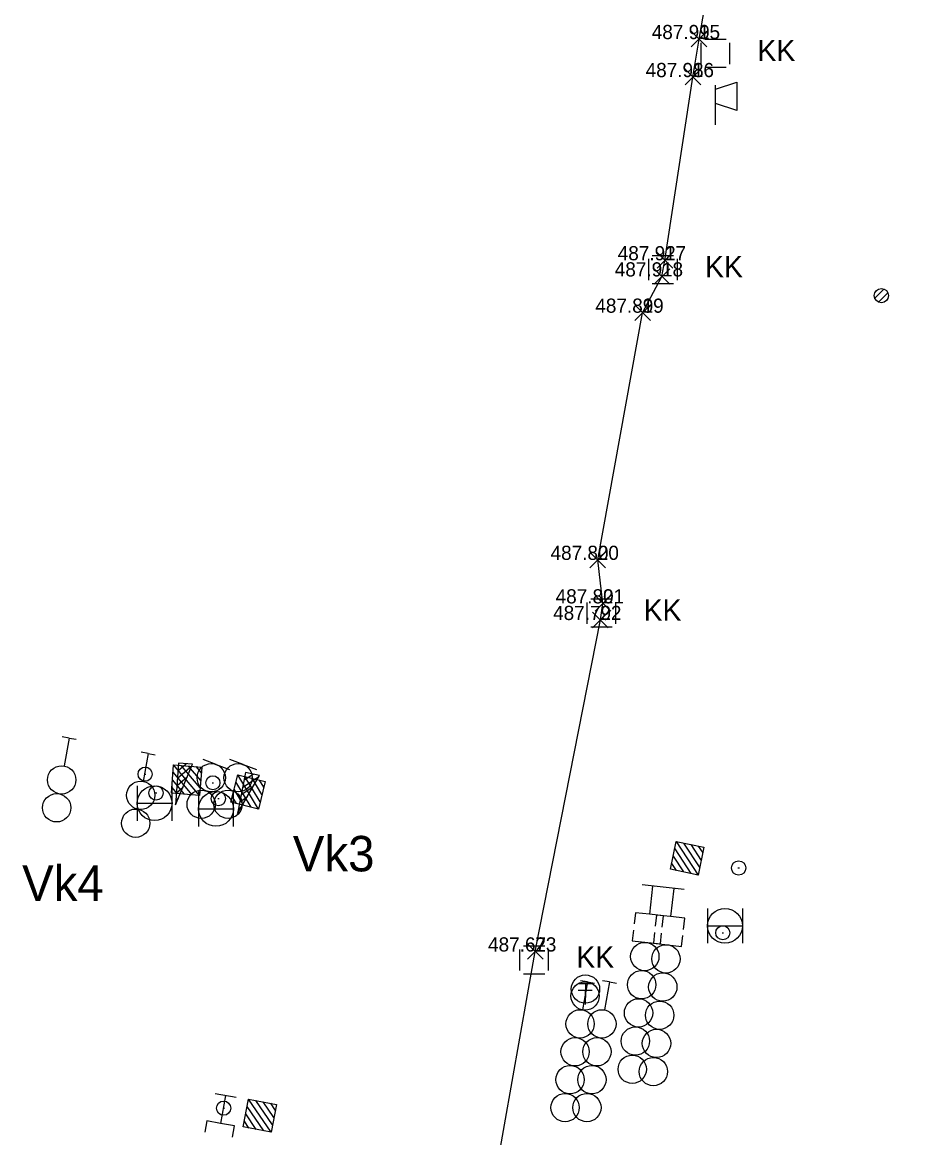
# Model space of a CAD drawing. Extents: x -874058 to -854960, y -10531873 to -1049126.
# Drawn here: x -866538.1 to -866474.7, y -1050102.6 to -1050024 of the extents above; entities that cross this region are included whole.
import ezdxf

# ---------------------------------------------------------------- set-up
doc = ezdxf.new("R2010")
doc.units = 0
for name, color, linetype in [('Vrstva 2', 7, 'Continuous'), ('Vrstva 3', 7, 'Continuous'), ('Vrstva 32', 7, 'Continuous'), ('Vrstva 33', 7, 'Continuous'), ('Vrstva 35', 7, 'Continuous'), ('Vrstva 36', 7, 'Continuous'), ('Vrstva 50', 7, 'Continuous'), ('Vrstva 6', 7, 'Continuous'), ('Vrstva 60', 7, 'Continuous'), ('Vrstva 61', 7, 'Continuous')]:
    doc.layers.add(name, color=color, linetype=linetype)

msp = doc.modelspace()

# ---------------------------------------------------------------- linework, layer by layer
at = {"layer": 'Vrstva 3'}
for p, q in [((-866526.085, -1050078.435), (-866527.432, -1050076.852)), ((-866525.557, -1050078.477), (-866527.39, -1050076.323)), ((-866527.112, -1050077.254), (-866526.091, -1050076.381)), ((-866527.073, -1050076.73), (-866526.494, -1050076.246)), ((-866527.036, -1050076.215), (-866527.018, -1050076.208)), ((-866525.514, -1050077.949), (-866526.862, -1050076.366)), ((-866525.472, -1050077.419), (-866526.332, -1050076.408)), ((-866525.429, -1050076.891), (-866525.804, -1050076.451)), ((-866522.308, -1050076.883), (-866522.29, -1050076.878)), ((-866526.614, -1050078.392), (-866527.475, -1050077.381)), ((-866527.15, -1050077.777), (-866526.41, -1050077.148)), ((-866521.924, -1050079.315), (-866522.997, -1050077.534)), ((-866521.41, -1050079.442), (-866522.869, -1050077.019)), ((-866522.511, -1050077.904), (-866521.391, -1050077.163)), ((-866522.409, -1050077.389), (-866521.775, -1050076.98)), ((-866521.282, -1050078.928), (-866522.355, -1050077.147)), ((-866521.154, -1050078.413), (-866521.839, -1050077.275)), ((-866521.027, -1050077.898), (-866521.325, -1050077.403)), ((-866529.972, -1050077.798), (-866529.972, -1050080.262)), ((-866527.142, -1050078.35), (-866527.517, -1050077.909)), ((-866527.508, -1050077.798), (-866527.508, -1050080.262)), ((-866527.189, -1050078.301), (-866526.721, -1050077.897)), ((-866525.642, -1050078.198), (-866525.642, -1050080.662)), ((-866523.178, -1050078.198), (-866523.178, -1050080.662)), ((-866522.44, -1050079.187), (-866523.125, -1050078.049)), ((-866522.613, -1050078.419), (-866521.801, -1050077.885)), ((-866529.972, -1050079.03), (-866527.508, -1050079.03)), ((-866527.228, -1050078.824), (-866527.048, -1050078.662)), ((-866522.954, -1050079.059), (-866523.252, -1050078.564)), ((-866522.817, -1050079.449), (-866522.619, -1050079.31)), ((-866522.715, -1050078.934), (-866522.201, -1050078.591)), ((-866525.642, -1050079.43), (-866523.178, -1050079.43)), ((-866492.032, -1050082.252), (-866490.893, -1050083.991)), ((-866491.924, -1050081.733), (-866490.374, -1050084.099)), ((-866491.405, -1050081.841), (-866490.266, -1050083.58)), ((-866490.885, -1050081.949), (-866490.158, -1050083.06)), ((-866490.366, -1050082.058), (-866490.049, -1050082.541)), ((-866492.14, -1050082.771), (-866491.413, -1050083.882)), ((-866492.249, -1050083.29), (-866491.932, -1050083.774)), ((-866489.722, -1050086.448), (-866489.722, -1050088.912)), ((-866487.258, -1050086.448), (-866487.258, -1050088.912)), ((-866489.722, -1050087.68), (-866487.258, -1050087.68)), ((-866498.83, -1050091.74), (-866497.83, -1050091.74)), ((-866498.33, -1050091.74), (-866498.33, -1050092.74)), ((-866498.856, -1050092.224), (-866497.856, -1050092.224)), ((-866498.356, -1050092.224), (-866498.356, -1050093.224)), ((-866521.032, -1050102.136), (-866522.203, -1050100.418)), ((-866520.511, -1050102.235), (-866522.104, -1050099.897)), ((-866520.412, -1050101.714), (-866521.583, -1050099.996)), ((-866520.314, -1050101.192), (-866521.061, -1050100.095)), ((-866520.215, -1050100.672), (-866520.541, -1050100.194)), ((-866521.554, -1050102.037), (-866522.301, -1050100.94)), ((-866522.074, -1050101.939), (-866522.4, -1050101.461))]:
    msp.add_line(p, q, dxfattribs=at)
for points in [[(-866527.55, -1050078.317), (-866527.39, -1050076.323), (-866525.396, -1050076.483), (-866525.557, -1050078.477)], [(-866527.55, -1050078.317), (-866527.39, -1050076.323), (-866525.396, -1050076.483), (-866525.557, -1050078.477)], [(-866523.351, -1050078.961), (-866522.869, -1050077.019), (-866520.928, -1050077.501), (-866521.41, -1050079.442)], [(-866523.351, -1050078.961), (-866522.869, -1050077.019), (-866520.928, -1050077.501), (-866521.41, -1050079.442)], [(-866489.966, -1050082.141), (-866490.374, -1050084.099), (-866492.332, -1050083.691), (-866491.924, -1050081.733)], [(-866489.966, -1050082.141), (-866490.374, -1050084.099), (-866492.332, -1050083.691), (-866491.924, -1050081.733)], [(-866522.476, -1050101.863), (-866522.104, -1050099.897), (-866520.139, -1050100.27), (-866520.511, -1050102.235)], [(-866522.476, -1050101.863), (-866522.104, -1050099.897), (-866520.139, -1050100.27), (-866520.511, -1050102.235)]]:
    msp.add_lwpolyline(points, close=True, dxfattribs=at)
for points in [[(-866527.55, -1050078.317), (-866527.39, -1050076.323), (-866525.396, -1050076.483), (-866525.557, -1050078.477), (-866527.55, -1050078.317)], [(-866527.55, -1050078.317), (-866527.39, -1050076.323), (-866525.396, -1050076.483), (-866525.557, -1050078.477), (-866527.55, -1050078.317)], [(-866527.251, -1050079.147), (-866526.049, -1050076.279), (-866527.035, -1050076.206), (-866527.251, -1050079.147)], [(-866527.251, -1050079.147), (-866526.049, -1050076.279), (-866527.035, -1050076.206), (-866527.251, -1050079.147)], [(-866522.88, -1050079.767), (-866521.337, -1050077.066), (-866522.307, -1050076.874), (-866522.88, -1050079.767)], [(-866522.88, -1050079.767), (-866521.337, -1050077.066), (-866522.307, -1050076.874), (-866522.88, -1050079.767)], [(-866523.351, -1050078.961), (-866522.869, -1050077.019), (-866520.928, -1050077.501), (-866521.41, -1050079.442), (-866523.351, -1050078.961)], [(-866523.351, -1050078.961), (-866522.869, -1050077.019), (-866520.928, -1050077.501), (-866521.41, -1050079.442), (-866523.351, -1050078.961)], [(-866489.966, -1050082.141), (-866490.374, -1050084.099), (-866492.332, -1050083.691), (-866491.924, -1050081.733), (-866489.966, -1050082.141)], [(-866489.966, -1050082.141), (-866490.374, -1050084.099), (-866492.332, -1050083.691), (-866491.924, -1050081.733), (-866489.966, -1050082.141)], [(-866522.476, -1050101.863), (-866522.104, -1050099.897), (-866520.139, -1050100.27), (-866520.511, -1050102.235), (-866522.476, -1050101.863)], [(-866522.476, -1050101.863), (-866522.104, -1050099.897), (-866520.139, -1050100.27), (-866520.511, -1050102.235), (-866522.476, -1050101.863)]]:
    msp.add_lwpolyline(points, dxfattribs=at)
for centre, radius in [((-866528.735, -1050079.029), 1.232), ((-866524.405, -1050079.429), 1.232), ((-866488.485, -1050087.679), 1.232), ((-866498.356, -1050092.624), 1), ((-866498.33, -1050092.14), 1)]:
    msp.add_circle(centre, radius, dxfattribs=at)
at = {"layer": 'Vrstva 32'}
msp.add_lwpolyline([(-866509.51, -1050138.604), (-866508.384, -1050128.298), (-866506.207, -1050113.936), (-866501.871, -1050089.486), (-866497.278, -1050066.106), (-866497.103, -1050064.945), (-866497.465, -1050061.872), (-866494.3, -1050044.444), (-866492.93, -1050041.876), (-866492.722, -1050040.744), (-866490.746, -1050027.824), (-866490.318, -1050025.144), (-866485.859, -1049999.669), (-866484.764, -1049995.807), (-866484.483, -1049994.606), (-866483.954, -1049988.671), (-866480.264, -1049968.241), (-866479.042, -1049964.21), (-866475.223, -1049944.101), (-866474.745, -1049941.586)], dxfattribs=at)
at = {"layer": 'Vrstva 33'}
msp.add_line((-866489.15, -1050031.18), (-866489.15, -1050028.38), dxfattribs=at)
msp.add_lwpolyline([(-866489.15, -1050028.68), (-866487.65, -1050028.18), (-866487.65, -1050030.18), (-866489.15, -1050029.68)], dxfattribs=at)
at = {"layer": 'Vrstva 35'}
for p, q in [((-866490.16, -1050026.9), (-866490.16, -1050025.4)), ((-866490.16, -1050026.9), (-866490.16, -1050025.4)), ((-866489.91, -1050025.15), (-866488.41, -1050025.15)), ((-866489.91, -1050025.15), (-866488.41, -1050025.15)), ((-866488.16, -1050025.4), (-866488.16, -1050026.9)), ((-866488.16, -1050025.4), (-866488.16, -1050026.9)), ((-866488.41, -1050027.15), (-866489.91, -1050027.15)), ((-866488.41, -1050027.15), (-866489.91, -1050027.15)), ((-866493.87, -1050042.14), (-866493.87, -1050040.64)), ((-866493.62, -1050040.39), (-866492.12, -1050040.39)), ((-866491.87, -1050040.64), (-866491.87, -1050042.14)), ((-866492.12, -1050042.39), (-866493.62, -1050042.39)), ((-866498.2, -1050066.37), (-866498.2, -1050064.87)), ((-866497.95, -1050064.62), (-866496.45, -1050064.62)), ((-866496.2, -1050064.87), (-866496.2, -1050066.37)), ((-866496.45, -1050066.62), (-866497.95, -1050066.62)), ((-866502.95, -1050090.84), (-866502.95, -1050089.34)), ((-866502.7, -1050089.09), (-866501.2, -1050089.09)), ((-866500.95, -1050089.34), (-866500.95, -1050090.84)), ((-866501.2, -1050091.09), (-866502.7, -1050091.09))]:
    msp.add_line(p, q, dxfattribs=at)
at = {"layer": 'Vrstva 36'}
for p, q in [((-866477.911, -1050043.414), (-866477.265, -1050042.768)), ((-866477.651, -1050043.684), (-866476.996, -1050043.029))]:
    msp.add_line(p, q, dxfattribs=at)
msp.add_circle((-866477.45, -1050043.23), 0.5, dxfattribs=at)
at = {"layer": 'Vrstva 50'}
for p, q in [((-866529.45, -1050076.98), (-866529.35, -1050076.98)), ((-866524.67, -1050077.59), (-866524.57, -1050077.59)), ((-866528.68, -1050078.31), (-866528.58, -1050078.31)), ((-866524.28, -1050078.71), (-866524.18, -1050078.71)), ((-866487.57, -1050083.6), (-866487.47, -1050083.6)), ((-866488.69, -1050088.17), (-866488.59, -1050088.17)), ((-866523.91, -1050100.54), (-866523.81, -1050100.54))]:
    msp.add_line(p, q, dxfattribs=at)
for centre in [(-866529.4, -1050076.98), (-866524.62, -1050077.59), (-866528.63, -1050078.31), (-866524.23, -1050078.71), (-866487.52, -1050083.6), (-866488.64, -1050088.17), (-866523.86, -1050100.54)]:
    msp.add_circle(centre, 0.5, dxfattribs=at)
at = {"layer": 'Vrstva 6'}
for p, q in [((-866534.762, -1050074.433), (-866535.254, -1050074.344)), ((-866534.762, -1050074.433), (-866535.115, -1050076.401)), ((-866534.762, -1050074.433), (-866534.269, -1050074.521)), ((-866529.18, -1050075.52), (-866529.672, -1050075.432)), ((-866529.18, -1050075.52), (-866529.533, -1050077.489)), ((-866529.18, -1050075.52), (-866528.688, -1050075.608)), ((-866524.38, -1050076.3), (-866525.315, -1050075.945)), ((-866522.486, -1050076.3), (-866523.421, -1050075.945)), ((-866524.38, -1050076.3), (-866523.445, -1050076.655)), ((-866522.486, -1050076.3), (-866521.551, -1050076.655)), ((-866492.845, -1050084.957), (-866494.336, -1050084.791)), ((-866493.591, -1050084.874), (-866493.591, -1050084.874)), ((-866491.355, -1050085.123), (-866492.845, -1050084.957)), ((-866492.1, -1050085.04), (-866492.1, -1050085.04)), ((-866498.18, -1050091.64), (-866498.672, -1050091.552)), ((-866498.18, -1050091.64), (-866498.533, -1050093.609)), ((-866498.18, -1050091.64), (-866497.688, -1050091.728)), ((-866496.64, -1050091.64), (-866497.132, -1050091.552)), ((-866496.64, -1050091.64), (-866496.993, -1050093.609)), ((-866496.64, -1050091.64), (-866496.148, -1050091.728)), ((-866522.982, -1050099.782), (-866524.458, -1050099.518)), ((-866523.72, -1050099.65), (-866523.72, -1050099.65))]:
    msp.add_line(p, q, dxfattribs=at)
for points in [[(-866493.591, -1050084.874), (-866493.812, -1050086.862), (-866494.806, -1050086.751), (-866494.894, -1050087.545)], [(-866492.1, -1050085.04), (-866492.321, -1050087.028), (-866493.315, -1050086.917), (-866493.403, -1050087.711)], [(-866492.907, -1050087.767), (-866492.818, -1050086.972), (-866493.812, -1050086.862)], [(-866491.416, -1050087.933), (-866491.327, -1050087.138), (-866492.321, -1050087.028)], [(-866494.943, -1050087.982), (-866495.027, -1050088.739), (-866493.039, -1050088.96), (-866492.955, -1050088.203)], [(-866493.452, -1050088.148), (-866493.536, -1050088.905), (-866491.549, -1050089.126), (-866491.464, -1050088.369)], [(-866523.72, -1050099.65), (-866524.073, -1050101.619), (-866525.057, -1050101.442), (-866525.198, -1050102.229)], [(-866523.23, -1050102.582), (-866523.089, -1050101.795), (-866524.073, -1050101.619)]]:
    msp.add_lwpolyline(points, dxfattribs=at)
for centre in [(-866535.291, -1050077.386), (-866524.735, -1050077.235), (-866522.841, -1050077.235), (-866529.71, -1050078.473), (-866535.644, -1050079.354), (-866525.444, -1050079.105), (-866523.55, -1050079.105), (-866530.063, -1050080.441), (-866494.144, -1050089.843), (-866492.653, -1050090.009), (-866494.365, -1050091.831), (-866492.874, -1050091.997), (-866494.586, -1050093.819), (-866493.095, -1050093.985), (-866498.709, -1050094.593), (-866497.169, -1050094.593), (-866494.807, -1050095.807), (-866493.317, -1050095.973), (-866499.062, -1050096.562), (-866497.522, -1050096.562), (-866495.029, -1050097.794), (-866493.538, -1050097.96), (-866499.415, -1050098.53), (-866497.875, -1050098.53), (-866499.768, -1050100.499), (-866498.228, -1050100.499)]:
    msp.add_circle(centre, 1, dxfattribs=at)
at = {"layer": 'Vrstva 60'}
for p, q in [((-866490.87, -1050025.69), (-866489.77, -1050024.59)), ((-866489.77, -1050025.69), (-866490.87, -1050024.59)), ((-866491.3, -1050028.37), (-866490.2, -1050027.27)), ((-866490.2, -1050028.37), (-866491.3, -1050027.27)), ((-866493.27, -1050041.29), (-866492.17, -1050040.19)), ((-866492.17, -1050041.29), (-866493.27, -1050040.19)), ((-866493.48, -1050042.43), (-866492.38, -1050041.33)), ((-866492.38, -1050042.43), (-866493.48, -1050041.33)), ((-866494.85, -1050044.99), (-866493.75, -1050043.89)), ((-866493.75, -1050044.99), (-866494.85, -1050043.89)), ((-866498.01, -1050062.42), (-866496.91, -1050061.32)), ((-866496.91, -1050062.42), (-866498.01, -1050061.32)), ((-866497.65, -1050065.49), (-866496.55, -1050064.39)), ((-866496.55, -1050065.49), (-866497.65, -1050064.39)), ((-866497.83, -1050066.66), (-866496.73, -1050065.56)), ((-866496.73, -1050066.66), (-866497.83, -1050065.56)), ((-866502.42, -1050090.04), (-866501.32, -1050088.94)), ((-866501.32, -1050090.04), (-866502.42, -1050088.94))]:
    msp.add_line(p, q, dxfattribs=at)

# ---------------------------------------------------------------- texts
at = {"layer": 'Vrstva 2'}
for s, p in [('Vk3', (-866518.979, -1050083.838)), ('Vk4', (-866538.082, -1050085.916))]:
    msp.add_text(s, height=2.5, dxfattribs=at).set_placement(p)
at = {"layer": 'Vrstva 35'}
for p in [(-866486.191, -1050026.692), (-866489.901, -1050041.932), (-866494.231, -1050066.162), (-866498.981, -1050090.632)]:
    msp.add_text('KK', height=1.5, dxfattribs=at).set_placement(p)
at = {"layer": 'Vrstva 60'}
for s, p in [('15', (-866490.32, -1050025.14)), ('16', (-866490.75, -1050027.82)), ('17', (-866492.72, -1050040.74)), ('18', (-866492.93, -1050041.88)), ('19', (-866494.3, -1050044.44)), ('20', (-866497.46, -1050061.87)), ('21', (-866497.1, -1050064.94)), ('22', (-866497.28, -1050066.11)), ('23', (-866501.87, -1050089.49))]:
    msp.add_text(s, height=1, dxfattribs=at).set_placement(p)
at = {"layer": 'Vrstva 61'}
for s, p in [('487.99 ', (-866493.653, -1050025.14)), ('487.98 ', (-866494.083, -1050027.82)), ('487.92 ', (-866496.053, -1050040.74)), ('487.91 ', (-866496.263, -1050041.88)), ('487.89 ', (-866497.633, -1050044.44)), ('487.80 ', (-866500.793, -1050061.87)), ('487.80 ', (-866500.433, -1050064.94)), ('487.79 ', (-866500.613, -1050066.11)), ('487.67 ', (-866505.203, -1050089.49))]:
    msp.add_text(s, height=1, dxfattribs=at).set_placement(p)

doc.saveas('drawing.dxf')
